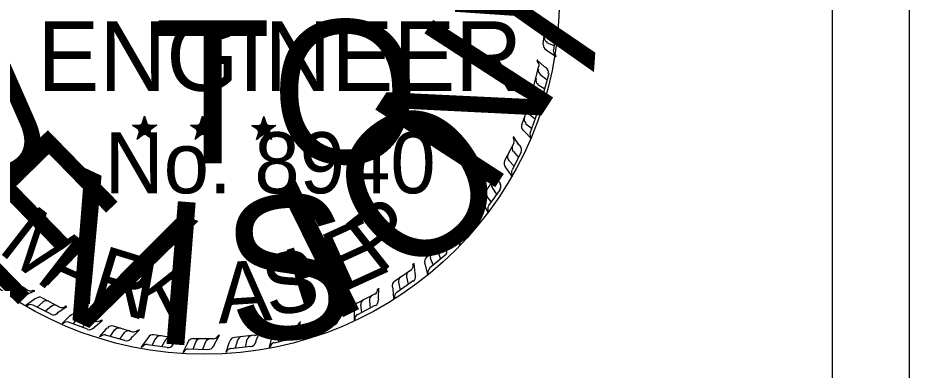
# Model space of a CAD drawing. Extents: x -23882 to 71394, y -5956005 to 2097152.
# Drawn here: x 64583 to 71046, y 1317567 to 1320117 of the extents above; entities that cross this region are included whole.
import ezdxf

# ---------------------------------------------------------------- set-up
doc = ezdxf.new("R2010")
doc.units = 0
for name, color, linetype in [('Level 62', 7, 'Continuous'), ('R_Border PE', 7, 'Continuous'), ('R_Border Prem', 7, 'Continuous')]:
    doc.layers.add(name, color=color, linetype=linetype)

msp = doc.modelspace()

# ---------------------------------------------------------------- linework, layer by layer
at = {"layer": 'Level 62'}
for points in [[(-16145.4, 1313329.8), (70490.4, 1313329.8), (70490.4, 1368514.8), (-16145.4, 1368514.8)], [(-15590.3, 1368514.8), (71045.5, 1368514.8), (71045.5, 1313329.8), (-15590.3, 1313329.8)]]:
    msp.add_lwpolyline(points, close=True, dxfattribs=at)
at = {"layer": 'R_Border PE'}
for p, q in [((68449.7, 1320071.6), (68388.4, 1320115)), ((68388.4, 1320115), (68396.1, 1320102.2)), ((68390.9, 1319925.8), (68408.8, 1320071.6)), ((68449.7, 1320071.6), (68442.1, 1320076.7)), ((68465.1, 1320069), (68449.7, 1320071.6)), ((68424.2, 1320010.2), (68477.9, 1319982.1)), ((68485.5, 1320025.5), (68467.6, 1319882.4)), ((68416.5, 1319938.6), (68470.2, 1319915.6)), ((68414, 1319884.9), (68424.2, 1319877.3)), ((68424.2, 1319877.3), (68485.5, 1319836.3)), ((68485.5, 1319836.3), (68483, 1319846.6)), ((68401.2, 1319762.2), (68344.9, 1319813.3)), ((68344.9, 1319813.3), (68352.6, 1319800.6)), ((68324.5, 1319624.1), (68360.3, 1319767.3)), ((68431.9, 1319713.6), (68393.5, 1319573)), ((68401.2, 1319762.2), (68396.1, 1319767.3)), ((68416.5, 1319754.5), (68401.2, 1319762.2)), ((68370.5, 1319706), (68419.1, 1319670.2)), ((68342.4, 1319583.2), (68355.2, 1319573)), ((68352.6, 1319634.4), (68403.7, 1319603.7)), ((68281, 1319532.1), (68278.5, 1319519.3)), ((68327, 1319478.4), (68281, 1319532.1)), ((68355.2, 1319573), (68406.3, 1319524.4)), ((68406.3, 1319524.4), (68406.3, 1319534.7)), ((68237.6, 1319345.5), (68288.7, 1319481)), ((68327, 1319478.4), (68321.9, 1319481)), ((68337.3, 1319468.2), (68327, 1319478.4)), ((65502, 1319404.3), (65486.7, 1319342.9)), ((65502, 1319404.3), (65491.8, 1319340.4)), ((65502, 1319404.3), (65496.9, 1319340.4)), ((65502, 1319312.2), (65502, 1319404.3)), ((65502, 1319404.3), (65519.9, 1319340.4)), ((65502, 1319404.3), (65514.8, 1319340.4)), ((65502, 1319404.3), (65507.1, 1319342.9)), ((65921.3, 1319404.3), (65908.5, 1319342.9)), ((65921.3, 1319404.3), (65911.1, 1319340.4)), ((65921.3, 1319404.3), (65918.7, 1319340.4)), ((65921.3, 1319312.2), (65921.3, 1319404.3)), ((65921.3, 1319404.3), (65939.2, 1319340.4)), ((65921.3, 1319404.3), (65934.1, 1319340.4)), ((65921.3, 1319404.3), (65929, 1319342.9)), ((66366.1, 1319401.7), (66353.4, 1319340.4)), ((66366.1, 1319401.7), (66358.5, 1319337.8)), ((66366.1, 1319401.7), (66363.6, 1319337.8)), ((66366.1, 1319309.7), (66366.1, 1319401.7)), ((66366.1, 1319401.7), (66384, 1319337.8)), ((66366.1, 1319401.7), (66378.9, 1319337.8)), ((66366.1, 1319401.7), (66373.8, 1319337.8)), ((68288.7, 1319422.2), (68334.7, 1319386.4)), ((68344.9, 1319422.2), (68296.4, 1319286.7)), ((65415.1, 1319340.4), (65502, 1319312.2)), ((65415.1, 1319340.4), (65479, 1319335.3)), ((65415.1, 1319340.4), (65479, 1319330.1)), ((65415.1, 1319340.4), (65476.4, 1319325)), ((65415.1, 1319340.4), (65476.4, 1319317.4)), ((65415.1, 1319340.4), (65473.9, 1319309.7)), ((65415.1, 1319340.4), (65473.9, 1319304.6)), ((65591.5, 1319340.4), (65502, 1319312.2)), ((65591.5, 1319340.4), (65512.2, 1319335.3)), ((65591.5, 1319340.4), (65517.3, 1319330.1)), ((65591.5, 1319340.4), (65517.3, 1319322.5)), ((65591.5, 1319340.4), (65532.7, 1319319.9)), ((65591.5, 1319340.4), (65537.8, 1319314.8)), ((65591.5, 1319340.4), (65542.9, 1319312.2)), ((65834.4, 1319340.4), (65921.3, 1319312.2)), ((65834.4, 1319340.4), (65898.3, 1319335.3)), ((65834.4, 1319340.4), (65898.3, 1319330.1)), ((65834.4, 1319340.4), (65895.7, 1319325)), ((65834.4, 1319340.4), (65893.2, 1319317.4)), ((65834.4, 1319340.4), (65893.2, 1319309.7)), ((65834.4, 1319340.4), (65893.2, 1319304.6)), ((66008.2, 1319340.4), (65921.3, 1319312.2)), ((66008.2, 1319340.4), (65931.5, 1319335.3)), ((66008.2, 1319340.4), (65939.2, 1319330.1)), ((66008.2, 1319340.4), (65939.2, 1319322.5)), ((66008.2, 1319340.4), (65954.5, 1319319.9)), ((66008.2, 1319340.4), (65959.6, 1319314.8)), ((66008.2, 1319340.4), (65962.2, 1319312.2)), ((66279.2, 1319337.8), (66366.1, 1319309.7)), ((66279.2, 1319337.8), (66343.1, 1319330.1)), ((66279.2, 1319337.8), (66343.1, 1319327.6)), ((66279.2, 1319337.8), (66340.6, 1319322.5)), ((66279.2, 1319337.8), (66340.6, 1319312.2)), ((66279.2, 1319337.8), (66338, 1319307.1)), ((66279.2, 1319337.8), (66338, 1319302)), ((66453.1, 1319337.8), (66366.1, 1319309.7)), ((66453.1, 1319337.8), (66376.4, 1319332.7)), ((66453.1, 1319337.8), (66384, 1319325)), ((66453.1, 1319337.8), (66384, 1319319.9)), ((66453.1, 1319337.8), (66396.8, 1319314.8)), ((66453.1, 1319337.8), (66404.5, 1319312.2)), ((66453.1, 1319337.8), (66407, 1319309.7)), ((68263.1, 1319353.2), (68306.6, 1319317.4)), ((65448.3, 1319238.1), (65502, 1319312.2)), ((65448.3, 1319238.1), (65476.4, 1319309.7)), ((65448.3, 1319238.1), (65479, 1319302)), ((65448.3, 1319238.1), (65484.1, 1319296.9)), ((65448.3, 1319238.1), (65491.8, 1319291.8)), ((65448.3, 1319238.1), (65502, 1319291.8)), ((65448.3, 1319238.1), (65504.6, 1319286.7)), ((65555.7, 1319238.1), (65502, 1319312.2)), ((65555.7, 1319238.1), (65502, 1319291.8)), ((65555.7, 1319238.1), (65502, 1319284.1)), ((65555.7, 1319238.1), (65512.2, 1319291.8)), ((65555.7, 1319238.1), (65519.9, 1319302)), ((65555.7, 1319238.1), (65522.5, 1319309.7)), ((65555.7, 1319238.1), (65527.6, 1319312.2)), ((65867.6, 1319238.1), (65921.3, 1319312.2)), ((65867.6, 1319238.1), (65895.7, 1319309.7)), ((65867.6, 1319238.1), (65900.8, 1319302)), ((65867.6, 1319238.1), (65903.4, 1319296.9)), ((65867.6, 1319238.1), (65911.1, 1319291.8)), ((65867.6, 1319238.1), (65921.3, 1319291.8)), ((65867.6, 1319238.1), (65923.8, 1319286.7)), ((65977.5, 1319238.1), (65921.3, 1319312.2)), ((65977.5, 1319238.1), (65921.3, 1319291.8)), ((65977.5, 1319238.1), (65921.3, 1319284.1)), ((65977.5, 1319238.1), (65931.5, 1319291.8)), ((65977.5, 1319238.1), (65939.2, 1319302)), ((65977.5, 1319238.1), (65941.7, 1319309.7)), ((65977.5, 1319238.1), (65946.9, 1319312.2)), ((66312.4, 1319235.5), (66366.1, 1319309.7)), ((66312.4, 1319235.5), (66340.6, 1319304.6)), ((66312.4, 1319235.5), (66345.7, 1319296.9)), ((66312.4, 1319235.5), (66348.2, 1319294.4)), ((66312.4, 1319235.5), (66358.5, 1319289.2)), ((66312.4, 1319235.5), (66366.1, 1319289.2)), ((66312.4, 1319235.5), (66368.7, 1319281.6)), ((66422.4, 1319235.5), (66366.1, 1319309.7)), ((66422.4, 1319235.5), (66366.1, 1319289.2)), ((66422.4, 1319235.5), (66366.1, 1319281.6)), ((66422.4, 1319235.5), (66376.4, 1319289.2)), ((66422.4, 1319235.5), (66386.6, 1319309.7)), ((66422.4, 1319235.5), (66386.6, 1319296.9)), ((66422.4, 1319235.5), (66391.7, 1319309.7)), ((68214.5, 1319197.2), (68176.2, 1319258.6)), ((68176.2, 1319258.6), (68176.2, 1319245.8)), ((68250.3, 1319302), (68258, 1319291.8)), ((68258, 1319291.8), (68306.6, 1319240.7)), ((68112.3, 1319079.6), (68181.3, 1319212.5)), ((68214.5, 1319197.2), (68212, 1319204.9)), ((68227.3, 1319187), (68214.5, 1319197.2)), ((68306.6, 1319240.7), (68306.6, 1319248.3)), ((68232.4, 1319143.5), (68166, 1319015.7)), ((68176.2, 1319148.6), (68212, 1319105.2)), ((68143, 1319084.7), (68178.7, 1319046.4)), ((68117.4, 1319036.1), (68125.1, 1319023.4)), ((68125.1, 1319023.4), (68166, 1318967.1)), ((67951.2, 1318826.5), (68035.6, 1318949.2)), ((68040.7, 1318995.2), (68035.6, 1318982.4)), ((68071.4, 1318931.3), (68040.7, 1318995.2)), ((68071.4, 1318931.3), (68066.3, 1318939)), ((68166, 1318967.1), (68168.5, 1318977.3)), ((68079, 1318875.1), (67994.7, 1318757.5)), ((68022.8, 1318887.9), (68053.5, 1318839.3)), ((68081.6, 1318921.1), (68071.4, 1318931.3)), ((67981.9, 1318826.5), (68015.1, 1318783)), ((67869.4, 1318752.4), (67864.3, 1318739.6)), ((67892.4, 1318683.3), (67869.4, 1318752.4)), ((67951.2, 1318783), (67958.9, 1318770.3)), ((67958.9, 1318770.3), (67992.1, 1318706.3)), ((67762, 1318591.3), (67859.2, 1318703.8)), ((67892.4, 1318683.3), (67889.9, 1318688.4)), ((67900.1, 1318670.5), (67892.4, 1318683.3)), ((67992.1, 1318706.3), (67994.7, 1318716.6)), ((67892.4, 1318624.5), (67795.3, 1318517.2)), ((67838.7, 1318647.5), (67864.3, 1318593.8)), ((67756.9, 1318547.8), (67759.5, 1318535)), ((67792.7, 1318591.3), (67818.3, 1318542.7)), ((67672.5, 1318524.8), (67667.4, 1318514.6)), ((67687.9, 1318455.8), (67672.5, 1318524.8)), ((67759.5, 1318535), (67787.6, 1318471.1)), ((67544.7, 1318384.2), (67654.7, 1318478.8)), ((67629.1, 1318425.1), (67647, 1318371.4)), ((67687.9, 1318455.8), (67685.3, 1318460.9)), ((67693, 1318440.5), (67687.9, 1318455.8)), ((67787.6, 1318471.1), (67790.1, 1318476.2)), ((67677.7, 1318397), (67567.7, 1318305)), ((67572.8, 1318376.5), (67593.3, 1318325.4)), ((67314.6, 1318210.4), (67437.3, 1318294.7)), ((67455.2, 1318338.2), (67445, 1318328)), ((67462.9, 1318266.6), (67455.2, 1318338.2)), ((67531.9, 1318340.7), (67537, 1318328)), ((67537, 1318328), (67552.4, 1318258.9)), ((64533.1, 1318225.7), (64655.8, 1318146.4)), ((67401.5, 1318241), (67411.8, 1318187.4)), ((67462.9, 1318266.6), (67462.9, 1318274.3)), ((67465.5, 1318253.8), (67462.9, 1318266.6)), ((67552.4, 1318258.9), (67557.5, 1318266.6)), ((67299.3, 1318166.9), (67301.8, 1318154.1)), ((67450.1, 1318212.9), (67330, 1318128.6)), ((67342.7, 1318202.7), (67355.5, 1318146.4)), ((64597, 1318156.7), (64551, 1318126)), ((64630.2, 1318100.4), (64640.4, 1318110.7)), ((64640.4, 1318110.7), (64706.9, 1318141.3)), ((64640.4, 1318110.7), (64645.6, 1318113.2)), ((64706.9, 1318141.3), (64694.1, 1318143.9)), ((67041.1, 1318051.9), (67171.5, 1318118.3)), ((67199.6, 1318159.2), (67189.4, 1318151.6)), ((67197, 1318090.2), (67194.5, 1318095.3)), ((67197, 1318090.2), (67199.6, 1318159.2)), ((67301.8, 1318154.1), (67307, 1318085.1)), ((64701.8, 1318077.4), (64643, 1318036.5)), ((64643, 1318036.5), (64653.2, 1318031.4)), ((64824.5, 1317972.6), (64694.1, 1318036.5)), ((64712, 1318085.1), (64701.8, 1318077.4)), ((64763.2, 1318059.5), (64722.3, 1318023.7)), ((64758, 1318090.2), (64888.4, 1318023.7)), ((67171.5, 1318034), (67046.2, 1317967.5)), ((67066.6, 1318039.1), (67074.3, 1317982.8)), ((67133.1, 1318069.7), (67138.2, 1318013.5)), ((67199.6, 1318072.3), (67197, 1318090.2)), ((67307, 1318085.1), (67314.6, 1318090.2)), ((64827.1, 1318028.8), (64783.6, 1317993.1)), ((64868, 1317975.2), (64875.6, 1317985.4)), ((64875.6, 1317985.4), (64937, 1318026.3)), ((64875.6, 1317985.4), (64883.3, 1317990.5)), ((64937, 1318026.3), (64924.2, 1318028.8)), ((65013.7, 1317975.2), (65146.6, 1317921.5)), ((66747.1, 1317929.1), (66887.7, 1317980.3)), ((66903, 1317947), (66915.8, 1318016.1)), ((66915.8, 1318016.1), (66905.6, 1318008.4)), ((67020.6, 1318013.5), (67020.6, 1317998.2)), ((67020.6, 1317998.2), (67020.6, 1317929.1)), ((64954.9, 1317954.7), (64903.8, 1317903.6)), ((64903.8, 1317903.6), (64914, 1317906.1)), ((65087.8, 1317862.7), (64949.8, 1317913.8)), ((64965.1, 1317962.4), (64954.9, 1317954.7)), ((65018.8, 1317947), (64983, 1317901)), ((65087.8, 1317918.9), (65049.5, 1317875.4)), ((65141.5, 1317880.6), (65197.8, 1317929.1)), ((65197.8, 1317929.1), (65182.4, 1317926.6)), ((66614.1, 1317847.3), (66632, 1317918.9)), ((66632, 1317918.9), (66624.3, 1317908.7)), ((66772.6, 1317911.2), (66772.6, 1317855)), ((66839.1, 1317936.8), (66839.1, 1317880.6)), ((66903, 1317947), (66905.6, 1317954.7)), ((66905.6, 1317931.7), (66903, 1317947)), ((67020.6, 1317929.1), (67025.7, 1317934.3)), ((65133.9, 1317870.3), (65141.5, 1317880.6)), ((65141.5, 1317880.6), (65144.1, 1317885.7)), ((65220.8, 1317862.7), (65174.8, 1317809)), ((65231, 1317870.3), (65220.8, 1317862.7)), ((65284.7, 1317860.1), (65248.9, 1317809)), ((65274.5, 1317888.2), (65415.1, 1317844.8)), ((65353.7, 1317839.7), (65320.5, 1317791.1)), ((65410, 1317803.9), (65463.7, 1317857.6)), ((65463.7, 1317857.6), (65448.3, 1317852.4)), ((66309.9, 1317780.9), (66340.6, 1317849.9)), ((66340.6, 1317849.9), (66327.8, 1317839.7)), ((66453.1, 1317852.4), (66596.2, 1317885.7)), ((66547.7, 1317847.3), (66542.5, 1317788.5)), ((66614.1, 1317847.3), (66614.1, 1317855)), ((66614.1, 1317832), (66614.1, 1317847.3)), ((66721.5, 1317878), (66708.7, 1317806.4)), ((66721.5, 1317890.8), (66721.5, 1317878)), ((66877.5, 1317895.9), (66742, 1317844.8)), ((65174.8, 1317809), (65182.4, 1317811.5)), ((65358.8, 1317780.9), (65218.2, 1317819.2)), ((65402.3, 1317791.1), (65410, 1317803.9)), ((65410, 1317803.9), (65415.1, 1317809)), ((65519.9, 1317793.6), (65476.4, 1317732.3)), ((65527.6, 1317803.9), (65519.9, 1317793.6)), ((65581.3, 1317798.8), (65555.7, 1317747.6)), ((65568.5, 1317824.3), (65714.2, 1317803.9)), ((65652.8, 1317786), (65624.7, 1317734.8)), ((65714.2, 1317763), (65760.2, 1317819.2)), ((65760.2, 1317819.2), (65747.4, 1317814.1)), ((65852.3, 1317796.2), (65998, 1317796.2)), ((65872.7, 1317773.2), (65852.3, 1317716.9)), ((66008.2, 1317755.3), (66044, 1317819.2)), ((66044, 1317819.2), (66033.8, 1317811.5)), ((66120.7, 1317775.7), (66113, 1317763)), ((66153.9, 1317806.4), (66299.7, 1317821.8)), ((66174.4, 1317783.4), (66159.1, 1317727.2)), ((66243.4, 1317791.1), (66230.6, 1317732.3)), ((66307.3, 1317765.5), (66309.9, 1317780.9)), ((66309.9, 1317780.9), (66312.4, 1317786)), ((66422.4, 1317801.3), (66404.5, 1317729.7)), ((66424.9, 1317814.1), (66422.4, 1317801.3)), ((66580.9, 1317798.8), (66440.3, 1317763)), ((66478.6, 1317832), (66473.5, 1317773.2)), ((66708.7, 1317806.4), (66716.4, 1317814.1)), ((65476.4, 1317732.3), (65486.7, 1317737.4)), ((65665.6, 1317729.7), (65522.5, 1317750.2)), ((65706.5, 1317747.6), (65714.2, 1317763)), ((65714.2, 1317763), (65716.8, 1317768.1)), ((65811.4, 1317757.8), (65778.1, 1317693.9)), ((65816.5, 1317770.6), (65811.4, 1317757.8)), ((65962.2, 1317714.4), (65816.5, 1317719.5)), ((65944.3, 1317770.6), (65921.3, 1317716.9)), ((66003.1, 1317740), (66008.2, 1317755.3)), ((66008.2, 1317755.3), (66010.8, 1317760.4)), ((66113, 1317763), (66090, 1317693.9)), ((66271.5, 1317737.4), (66125.8, 1317722.1)), ((66404.5, 1317729.7), (66414.7, 1317740)), ((65778.1, 1317693.9), (65785.8, 1317699)), ((66090, 1317693.9), (66097.7, 1317701.6))]:
    msp.add_line(p, q, dxfattribs=at)
for points in [[(65502, 1319404.3), (65555.7, 1319238.1), (65415.1, 1319340.4), (65591.5, 1319340.4), (65448.3, 1319238.1), (65502, 1319404.3)], [(65921.3, 1319404.3), (65977.5, 1319238.1), (65834.4, 1319340.4), (66008.2, 1319340.4), (65867.6, 1319238.1), (65921.3, 1319404.3)], [(66366.1, 1319401.7), (66422.4, 1319235.5), (66279.2, 1319337.8), (66453.1, 1319337.8), (66312.4, 1319235.5), (66366.1, 1319401.7)]]:
    msp.add_lwpolyline(points, dxfattribs=at)
for centre, radius in [((65502.1, 1319312.9), 43.3), ((65502.1, 1319312.9), 39.2), ((65502.1, 1319312.9), 36.4), ((65502.1, 1319312.9), 33.4), ((65502.1, 1319312.9), 29.1), ((65502.1, 1319312.9), 27), ((65502.1, 1319312.9), 24.9), ((65502.1, 1319312.9), 21.5), ((65502.1, 1319312.9), 18.8), ((65502.1, 1319312.9), 15.6), ((65502.1, 1319312.9), 12.5), ((65922.1, 1319312.9), 43.3), ((65922.1, 1319312.9), 39.2), ((65922.1, 1319312.9), 36.4), ((65922.1, 1319312.9), 33.4), ((65922.1, 1319312.9), 29.1), ((65922.1, 1319312.9), 27), ((65922.1, 1319312.9), 24.9), ((65922.1, 1319312.9), 21.5), ((65922.1, 1319312.9), 18.8), ((65922.1, 1319312.9), 15.6), ((65922.1, 1319312.9), 12.5), ((66366.8, 1319310), 43.3), ((66366.8, 1319310), 39.2), ((66366.8, 1319310), 36.4), ((66366.8, 1319310), 33.4), ((66366.8, 1319310), 29.1), ((66366.8, 1319310), 27), ((66366.8, 1319310), 24.9), ((66366.8, 1319310), 21.5), ((66366.8, 1319310), 18.8), ((66366.8, 1319310), 15.6), ((65502.1, 1319312.9), 9.3), ((65502.1, 1319312.9), 7.46), ((65502.1, 1319312.9), 3.63), ((65922.1, 1319312.9), 9.3), ((65922.1, 1319312.9), 7.46), ((65922.1, 1319312.9), 3.63), ((66366.8, 1319310), 12.5), ((66366.8, 1319310), 9.3), ((66366.8, 1319310), 7.46), ((66366.8, 1319310), 3.63)]:
    msp.add_circle(centre, radius, dxfattribs=at)
for centre, start, end in [((68370.9, 1320071.2), 357.57003, 56.35787), ((68447.1, 1320045.2), 173.30926, 241.68323), ((68443, 1320030.3), 353.30926, 61.68323), ((68438.6, 1319974.8), 173.30926, 241.68323), ((68432.3, 1319920), 173.30926, 241.68323), ((68504.5, 1319879.2), 177.57003, 236.35788), ((68323.1, 1319772.1), 350.44502, 49.23286), ((68395.6, 1319736.9), 166.18424, 234.55821), ((68389.7, 1319722.6), 346.18424, 54.55821), ((68378.4, 1319668.1), 166.18424, 234.55821), ((68365.4, 1319614.5), 166.18424, 234.55821), ((68249.6, 1319492.8), 344.1611, 42.94894), ((68431.9, 1319565), 170.44502, 229.23286), ((68317.7, 1319449.9), 159.90033, 228.2743), ((68310.3, 1319436.3), 339.90033, 48.2743), ((68293.1, 1319383.4), 159.90033, 228.2743), ((68274.3, 1319331.6), 159.90033, 228.2743), ((68335, 1319275.1), 164.1611, 222.94894), ((68142.8, 1319225.3), 337.11492, 35.90277), ((68172.6, 1319111.3), 152.85415, 221.22812), ((68205.2, 1319174.3), 152.85415, 221.22812), ((68196.2, 1319161.7), 332.85415, 41.22812), ((68147.6, 1319062.2), 152.85415, 221.22812), ((68200.9, 1318998.6), 157.11492, 215.90277), ((68001, 1318967.8), 329.7262, 28.51404), ((68015.8, 1318850.9), 145.46542, 213.83939), ((68056.3, 1318909.2), 145.46542, 213.83939), ((68045.7, 1318897.9), 325.46542, 33.83939), ((67984.7, 1318805.4), 145.46542, 213.83939), ((67827.1, 1318726.8), 322.78215, 21.56999), ((68029.5, 1318735.6), 149.7262, 208.51404), ((67874.9, 1318662), 138.52138, 206.89535), ((67827.7, 1318609), 138.52138, 206.89535), ((67863, 1318652), 318.52138, 26.89535), ((67791.3, 1318567.6), 138.52138, 206.89535), ((67628.6, 1318507.1), 314.78258, 13.57042), ((67827.3, 1318492.8), 142.78215, 201.56999), ((67612.8, 1318390.4), 130.5218, 198.89578), ((67666.9, 1318436.3), 130.5218, 198.89578), ((67653.8, 1318428.1), 310.5218, 18.89578), ((67571, 1318354.5), 130.5218, 198.89578), ((67409.6, 1318324.1), 308.91341, 7.70125), ((67596.2, 1318275.4), 134.78258, 193.57042), ((67381.9, 1318209.6), 124.65263, 193.0266), ((67440.5, 1318249.7), 124.65263, 193.0266), ((67426.6, 1318242.9), 304.65263, 13.0266), ((64617.3, 1318123.8), 56.17359, 124.54756), ((67336.7, 1318178.1), 124.65263, 193.0266), ((64605.8, 1318134.2), 236.17359, 304.54756), ((64675.1, 1318179.8), 240.43436, 299.22221), ((67171.7, 1318073.8), 116.83862, 185.21259), ((67151.2, 1318151.7), 301.09939, 359.88724), ((67353.7, 1318096.9), 128.91341, 187.70125), ((64677, 1318001.3), 67.33158, 126.11942), ((64740.4, 1318054.9), 63.0708, 131.44477), ((64789.6, 1318030.1), 63.0708, 131.44477), ((64852.7, 1317997.7), 63.0708, 131.44477), ((67059.2, 1318017), 116.83862, 185.21259), ((67108.3, 1318042.1), 116.83862, 185.21259), ((67157, 1318069), 296.83862, 5.21259), ((64840.1, 1318006.7), 243.0708, 311.44478), ((64903.4, 1318060.3), 247.33158, 306.11942), ((64997.3, 1317936.3), 69.09549, 137.46946), ((66879.8, 1317935.2), 110.47236, 178.84634), ((66868.1, 1318014.9), 294.73314, 353.52098), ((67065, 1317934.3), 121.09939, 179.88724), ((64939.9, 1317876.4), 73.35627, 132.14411), ((65048.8, 1317916.8), 69.09549, 137.46946), ((65115, 1317891.3), 69.09549, 137.46946), ((65158.9, 1317958.8), 253.35627, 312.14411), ((66585.1, 1317921.1), 288.1674, 346.95524), ((66761.7, 1317891.2), 110.47236, 178.84634), ((66813.3, 1317910.6), 110.47236, 178.84634), ((66864.7, 1317932), 290.47236, 358.84634), ((65101.5, 1317898.9), 249.09549, 317.46946), ((65263.4, 1317847.1), 73.99093, 142.3649), ((65316.4, 1317832), 73.99093, 142.3649), ((65384.5, 1317812.2), 73.99093, 142.3649), ((65422.5, 1317883.2), 258.25171, 317.03955), ((66292.4, 1317856.9), 279.92492, 338.71276), ((66465.2, 1317810.4), 103.90663, 172.2806), ((66518.7, 1317823.9), 103.90663, 172.2806), ((66587.6, 1317840.6), 103.90663, 172.2806), ((66758.3, 1317808.3), 114.73314, 173.52098), ((65211.3, 1317782.5), 78.25171, 137.03955), ((65370.4, 1317818.6), 253.99093, 322.3649), ((65562, 1317783.8), 81.42307, 149.79704), ((65616.5, 1317775.8), 81.42307, 149.79704), ((65686.6, 1317764.9), 81.42307, 149.79704), ((65715, 1317840.3), 265.68385, 324.47169), ((65853.7, 1317755.8), 89.16284, 157.53681), ((65908.8, 1317755.1), 89.16284, 157.53681), ((65979.7, 1317753.8), 89.16284, 157.53681), ((65997.8, 1317832.3), 273.42361, 332.21146), ((66157.9, 1317764.5), 95.66414, 164.03812), ((66212.7, 1317770.1), 95.66414, 164.03812), ((66283.4, 1317776.8), 95.66414, 164.03812), ((66572.2, 1317839.2), 283.90663, 352.2806), ((65518.7, 1317713.1), 85.68385, 144.47169), ((65671.8, 1317769.5), 261.42307, 329.79704), ((65820.4, 1317679.8), 93.42361, 152.21146), ((65964.4, 1317756.3), 269.16284, 337.53681), ((66133.4, 1317685.3), 99.92492, 158.71276), ((66267.9, 1317777.6), 275.66414, 344.03812), ((66452.3, 1317728.5), 108.1674, 166.95524)]:
    msp.add_arc(centre, 39.7, start, end, dxfattribs=at)
at = {"layer": 'R_Border Prem'}
msp.add_circle((65935, 1320255.6), 2574.3, dxfattribs=at)

# ---------------------------------------------------------------- texts
at = {"layer": 'R_Border PE'}
for s, height, p in [('ENGINEER', 503.24, (64724.8, 1319588.4)), ('No. 8940', 442.1, (65213.1, 1318846.9))]:
    msp.add_text(s, height=height, dxfattribs=at).set_placement(p)
for s, height, rotation, p in [('M', 440.4, 322.16225, (64428.2, 1318430.2)), ('R', 440.4, 38.39464, (67197, 1318251.3)), ('E', 440.4, 24.5342, (66933.7, 1318126)), ('A', 440.4, 336.02269, (64747.8, 1318202.7)), ('H', 440.3, 17.60399, (66619.2, 1318003.3)), ('R', 440.4, 342.9529, (65082.7, 1318051.9)), ('S', 440.4, 10.67377, (66404.5, 1317949.6)), ('K', 440.4, 349.88312, (65397.2, 1317957.3)), ('A', 440.4, 3.74355, (66038.9, 1317903.6))]:
    msp.add_text(s, height=height, rotation=rotation, dxfattribs=at).set_placement(p)
at = {"layer": 'R_Border Prem'}
for s, rotation, p in [('Y', 266.11312, (67787.7, 1320684.7)), ('N', 57.13775, (67982.6, 1318795.6)), ('R', 293.76387, (63534.5, 1319473.1)), ('O', 36.57544, (67353.8, 1318180.2)), ('E', 314.32618, (63980.5, 1318661.4)), ('V', 334.8885, (64621.9, 1318096.5)), ('I', 26.29428, (66826.4, 1317894)), ('S', 5.73197, (66133.3, 1317750.7)), ('I', 355.45081, (65533.7, 1317767.4))]:
    msp.add_text(s, height=1035.4, rotation=rotation, dxfattribs=at).set_placement(p)
msp.add_text('TO', height=1035.44, dxfattribs=at).set_placement((65573, 1319064.6))

doc.saveas('drawing.dxf')
